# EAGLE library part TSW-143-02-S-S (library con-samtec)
THROUGH-HOLE .025" SQ POST HEADER Source: Samtec TSW.pdf
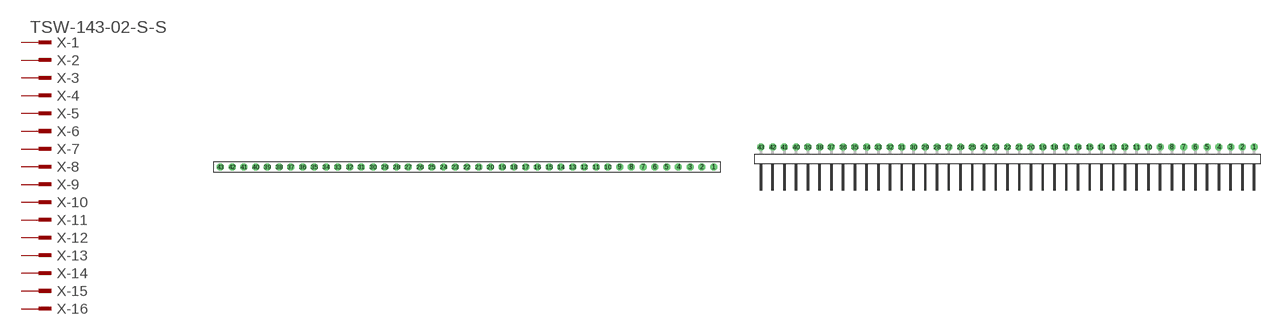
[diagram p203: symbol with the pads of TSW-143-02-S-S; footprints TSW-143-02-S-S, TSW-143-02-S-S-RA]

Designator prefix X; gates -1=MPINV -2=MPIN -3=MPIN -4=MPIN -5=MPIN -6=MPIN -7=MPIN -8=MPIN -9=MPIN -10=MPIN -11=MPIN -12=MPIN -13=MPIN -14=MPIN -15=MPIN -16=MPIN -17=MPIN -18=MPIN -19=MPIN -20=MPIN -21=MPIN -22=MPIN -23=MPIN -24=MPIN -25=MPIN -26=MPIN -27=MPIN -28=MPIN -29=MPIN -30=MPIN -31=MPIN -32=MPIN -33=MPIN -34=MPIN -35=MPIN -36=MPIN -37=MPIN -38=MPIN -39=MPIN -40=MPIN -41=MPIN -42=MPIN -43=MPIN

## TSW-143-02-S-S (OC_FARNELL: unknown; OC_NEWARK: unknown)  [TSW-143-02-S-S]
1  -1:1  pas
2  -2:1  pas
3  -3:1  pas
4  -4:1  pas
5  -5:1  pas
6  -6:1  pas
7  -7:1  pas
8  -8:1  pas
9  -9:1  pas
10  -10:1  pas
11  -11:1  pas
12  -12:1  pas
13  -13:1  pas
14  -14:1  pas
15  -15:1  pas
16  -16:1  pas
17  -17:1  pas
18  -18:1  pas
19  -19:1  pas
20  -20:1  pas
21  -21:1  pas
22  -22:1  pas
23  -23:1  pas
24  -24:1  pas
25  -25:1  pas
26  -26:1  pas
27  -27:1  pas
28  -28:1  pas
29  -29:1  pas
30  -30:1  pas
31  -31:1  pas
32  -32:1  pas
33  -33:1  pas
34  -34:1  pas
35  -35:1  pas
36  -36:1  pas
37  -37:1  pas
38  -38:1  pas
39  -39:1  pas
40  -40:1  pas
41  -41:1  pas
42  -42:1  pas
43  -43:1  pas

## TSW-143-02-S-S-RA (OC_FARNELL: unknown; OC_NEWARK: unknown)  [TSW-143-02-S-S-RA]
Pads as for TSW-143-02-S-S

## Footprint TSW-143-02-S-S (pad centres in mm)
THROUGH-HOLE .025" SQ POST HEADER Source: Samtec TSW.pdf
drill 1 pad 1.5 octagon: 1 53.34,0; 2 50.8,0; 3 48.26,0; 4 45.72,0; 5 43.18,0; 6 40.64,0; 7 38.1,0; 8 35.56,0; 9 33.02,0; 10 30.48,0; 11 27.94,0; 12 25.4,0; 13 22.86,0; 14 20.32,0; 15 17.78,0; 16 15.24,0; 17 12.7,0; 18 10.16,0; 19 7.62,0; 20 5.08,0; 21 2.54,0; 22 0,0; 23 -2.54,0; 24 -5.08,0; 25 -7.62,0; 26 -10.16,0; 27 -12.7,0; 28 -15.24,0; 29 -17.78,0; 30 -20.32,0; 31 -22.86,0; 32 -25.4,0; 33 -27.94,0; 34 -30.48,0; 35 -33.02,0; 36 -35.56,0; 37 -38.1,0; 38 -40.64,0; 39 -43.18,0; 40 -45.72,0; 41 -48.26,0; 42 -50.8,0; 43 -53.34,0

## Footprint TSW-143-02-S-S-RA (pad centres in mm)
THROUGH-HOLE .025" SQ POST HEADER Source: Samtec TSW.pdf
drill 1 pad 1.5 octagon: 1 53.34,1.524; 2 50.8,1.524; 3 48.26,1.524; 4 45.72,1.524; 5 43.18,1.524; 6 40.64,1.524; 7 38.1,1.524; 8 35.56,1.524; 9 33.02,1.524; 10 30.48,1.524; 11 27.94,1.524; 12 25.4,1.524; 13 22.86,1.524; 14 20.32,1.524; 15 17.78,1.524; 16 15.24,1.524; 17 12.7,1.524; 18 10.16,1.524; 19 7.62,1.524; 20 5.08,1.524; 21 2.54,1.524; 22 0,1.524; 23 -2.54,1.524; 24 -5.08,1.524; 25 -7.62,1.524; 26 -10.16,1.524; 27 -12.7,1.524; 28 -15.24,1.524; 29 -17.78,1.524; 30 -20.32,1.524; 31 -22.86,1.524; 32 -25.4,1.524; 33 -27.94,1.524; 34 -30.48,1.524; 35 -33.02,1.524; 36 -35.56,1.524; 37 -38.1,1.524; 38 -40.64,1.524; 39 -43.18,1.524; 40 -45.72,1.524; 41 -48.26,1.524; 42 -50.8,1.524; 43 -53.34,1.524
